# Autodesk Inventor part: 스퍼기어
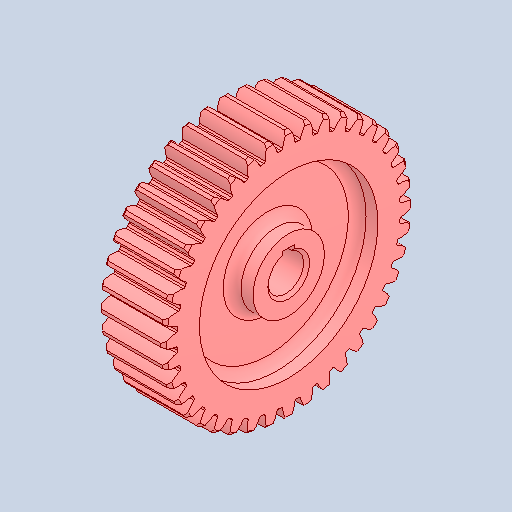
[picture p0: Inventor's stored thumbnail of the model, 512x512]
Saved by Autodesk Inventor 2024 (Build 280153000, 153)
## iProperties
Created: 2024-11
Part Number: 스퍼기어
Material: 강철, 탄소
Document SubType Name: Modeling
Designer: user
Density: 7.85 g/cm^3
Appearance: 기본값
Author: jhkim
Sending System: Autodesk Inventor 2025
Preprocessor: ST-DEVELOPER v20
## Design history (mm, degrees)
node "스퍼기어1"
node "솔리드2"
node "솔리드1"
